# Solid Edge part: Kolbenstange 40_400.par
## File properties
Username: ahadarics
Dokumentum tartalom típus: 0
Author: ahadarics
Last saved by: ahadarics
Revision: 89
Sűrűség: 0,000 kg/m^3
Pontosság: 0,990
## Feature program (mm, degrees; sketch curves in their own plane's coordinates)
base feature "unnamed BaseFeature 1"
thread "unnamed Thread 1"
chamfer "Letörés_1"  SetBackValue2 = 20 deg
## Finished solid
Body 1: solid body, 21 faces, 32 edges, 14 vertices.
  Faces by surface: plane 8, cylinder 5, cone 4, torus 4
  Edges by curve: circle 17, line 9, curve on surface 4, ellipse 2
Bounding box of the edges (mm; curved faces can reach further): 40.000 x 40.000 x 528.000, from (-20, -20, -78) to (20, 20, 450).
Cylindrical faces by radius (mm): R5 x1, R6 x1, R7.75 x1, R8 x1, R20 x1
Conical faces (half-angle, radius in mm at the cone's reference point): 20 deg R6 x1, 30 deg R7.875 x1, 45 deg R19.6 x1, 60 deg R5.5 x1
Toroidal faces (ring radius, tube radius in mm): R5.4 r0.4 x2, R6.55 r1.2 x2
Planar faces by outward normal: +x 1, +z 3, -x 1, -z 1, oblique 2
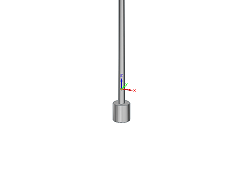
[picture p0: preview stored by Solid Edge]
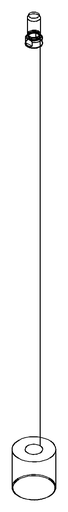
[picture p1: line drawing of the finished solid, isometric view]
